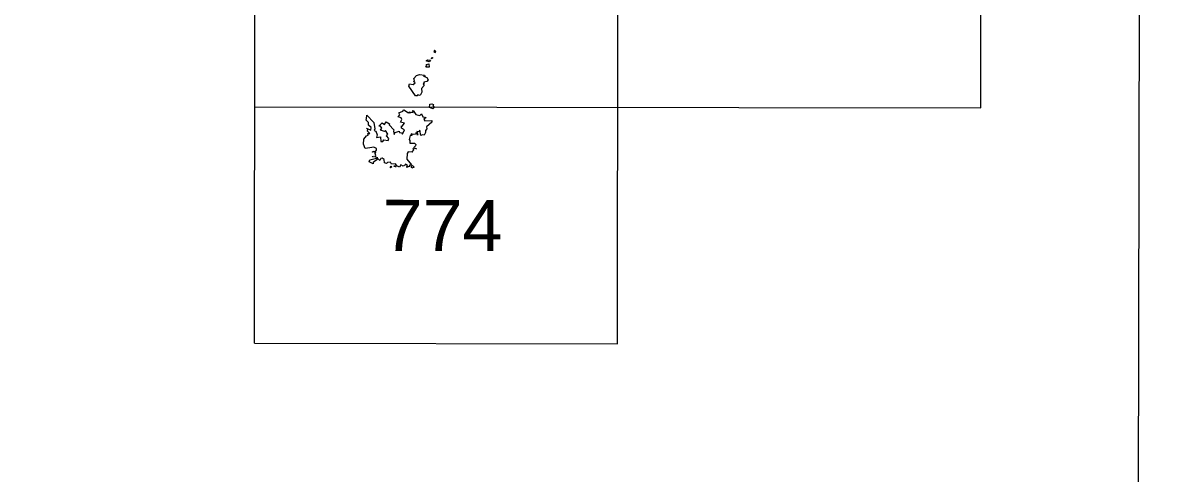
# Model space of a CAD drawing. Extents: x -807245 to 6129983, y -54972206 to 262146364.
# Drawn here: x 491598.6 to 492038.7, y 4383013.6 to 4383185.9 of the extents above; entities that cross this region are included whole.
import ezdxf
from ezdxf.enums import TextEntityAlignment as Align

# ---------------------------------------------------------------- set-up
doc = ezdxf.new("R2010")
doc.units = 0
doc.header["$LTSCALE"] = 4
doc.linetypes.add('DOTTED', pattern=[1.5, 0.3, -1.2])
for name, color, linetype, lineweight in [('1', 7, 'Continuous', 13), ('2', 7, 'DOTTED', 13), ('27', 7, 'Continuous', 25), ('3', 7, 'Continuous', 25)]:
    doc.layers.add(name, color=color, linetype=linetype, lineweight=lineweight)

msp = doc.modelspace()

# ---------------------------------------------------------------- linework, layer by layer
at = {"layer": '1', "lineweight": 25}
for p, q in [((491686.92, 4383063.58), (491687.71, 4383605.53)), ((491825.48, 4383063.38), (491826.27, 4383605.33)), ((491964.17, 4383153.49), (491964.83, 4383605.13)), ((491687.05, 4383153.89), (491964.17, 4383153.49)), ((491686.92, 4383063.57), (491825.48, 4383063.37))]:
    msp.add_line(p, q, dxfattribs=at)
msp.add_lwpolyline([(487426.46, 4384475.71), (492026.46, 4384469.03), (492021.81, 4381264.03), (487421.81, 4381270.71)], close=True, dxfattribs=at)
at = {"layer": '27'}
msp.add_spline([(491255.21, 4383970.03), (491244.34, 4383967.52), (491230.36, 4383957.66), (491230.81, 4383957.81), (491230.81, 4383957.81), (491220.15, 4383951.47), (491212.7, 4383943.01), (491205.06, 4383944.23), (491184.85, 4383957.71), (491152.82, 4383981.27), (491128.36, 4384004.58), (491128.29, 4384004.88), (491122.26, 4384021.39), (491095.75, 4384034.59), (491071.07, 4384059.32), (491064.71, 4384065.12)], degree=3, dxfattribs=at)
at = {"layer": '3'}
for points in [[(491753.04, 4383171.84), (491754.17, 4383171.75), (491753.59, 4383171.07), (491752.52, 4383171.55)], [(491754.62, 4383172.8), (491755.02, 4383172.65), (491754.51, 4383172.21)], [(491755.7, 4383175.51), (491755.43, 4383174.99), (491755.98, 4383174.7), (491756.14, 4383175.02)], [(491753.57, 4383170.28), (491753.59, 4383169.01), (491752.4, 4383169.13), (491752.79, 4383169.66), (491752.46, 4383170.12)], [(491749.38, 4383143.39), (491749.18, 4383143.08), (491749.1, 4383143.54)], [(491748.39, 4383138.11), (491748.83, 4383137.91), (491748.03, 4383137.98)], [(491732.15, 4383135.07), (491732.37, 4383134.87), (491731.99, 4383134.85)], [(491738.73, 4383130.75), (491739.11, 4383131.26), (491739.43, 4383131.01), (491738.93, 4383130.55)], [(491740.34, 4383131.09), (491740.37, 4383131.47), (491741.03, 4383130.98)], [(491747.24, 4383131.44), (491747.89, 4383130.92), (491746.99, 4383130.43), (491746.79, 4383131.31)]]:
    msp.add_lwpolyline(points, close=True, dxfattribs=at)
for points in [[(491750.24, 4383158.28), (491749.31, 4383158.53), (491749.12, 4383158.16), (491748.37, 4383158.13), (491745.86, 4383161.8), (491746.1, 4383162.75), (491747.5, 4383162.4), (491748.25, 4383163.08), (491747.68, 4383163.63), (491748.04, 4383163.87), (491747.85, 4383164.75), (491748.81, 4383165.83)], [(491748.81, 4383165.83), (491749.98, 4383166.22), (491751.89, 4383166.07), (491752.14, 4383165.56), (491751.52, 4383165.57), (491752.76, 4383165.16), (491753.31, 4383164.18), (491752.7, 4383163.57), (491751.6, 4383163.28), (491751.9, 4383163.1), (491751.42, 4383162.75), (491751.77, 4383162.01), (491750.76, 4383160.97), (491750.89, 4383159.49), (491750.24, 4383158.28)], [(491753.79, 4383153.7), (491753.96, 4383154.95), (491754.68, 4383155.05), (491755.29, 4383154.82), (491755.08, 4383154.41), (491755.55, 4383153.71)], [(491730.99, 4383138.31), (491729.19, 4383138.04), (491728.58, 4383139.7), (491728.76, 4383141.61), (491729.68, 4383142.82), (491730.42, 4383143.06), (491730.27, 4383143.71), (491730.97, 4383143.72), (491730.13, 4383144.66), (491730.29, 4383145.27), (491729.71, 4383145.72), (491731.43, 4383145.06), (491731.52, 4383146.04), (491730.51, 4383146.95), (491730.44, 4383147.92), (491729.61, 4383148.81), (491729.69, 4383149.5)], [(491729.69, 4383149.5), (491729.87, 4383150.69), (491732.53, 4383147.94), (491732.88, 4383145.56), (491732.64, 4383144.82), (491733.32, 4383144.63), (491733.85, 4383143.16), (491733.53, 4383142.24), (491735.11, 4383142.51), (491735.24, 4383140.65), (491735.91, 4383140.69), (491736.32, 4383141.35), (491738, 4383141), (491738.21, 4383141.76)], [(491743.38, 4383146.58), (491744.25, 4383147.65), (491742.68, 4383148), (491743.18, 4383149.05), (491742.95, 4383149.7), (491741.85, 4383150.04), (491742.46, 4383150.82), (491742.1, 4383151.64), (491743.58, 4383152.2), (491743.92, 4383152.75), (491745.71, 4383151.67)], [(491745.71, 4383151.67), (491745.92, 4383151.97), (491746.22, 4383151.51), (491746.64, 4383151.87), (491747.6, 4383151.76), (491747.26, 4383152.15), (491747.59, 4383152.56), (491748.52, 4383151.02), (491750.09, 4383150.55), (491750.74, 4383151.18), (491751.28, 4383150.07), (491752.45, 4383149.89), (491751.6, 4383149.23), (491752.01, 4383148.54), (491754.65, 4383148.66), (491754.63, 4383148.07), (491752.61, 4383146.31), (491752.78, 4383145.51), (491752.25, 4383144.91), (491752.31, 4383144.09)], [(491755.55, 4383153.71), (491755.04, 4383153.13), (491753.79, 4383153.7)], [(491738.21, 4383141.76), (491737.42, 4383142.86), (491737.92, 4383143.51), (491736.96, 4383144.81), (491736.57, 4383144.53), (491735.08, 4383145.05), (491735.57, 4383145.82), (491735.02, 4383146.56), (491734.45, 4383146.55), (491735.76, 4383147.83), (491736.66, 4383147.18), (491737.25, 4383148.2)], [(491737.25, 4383148.2), (491738.51, 4383147.38), (491738.37, 4383147.07), (491740.22, 4383145.19), (491740, 4383144.65), (491740.32, 4383143.34), (491740.69, 4383144.08), (491742.18, 4383144.57), (491742.26, 4383144.07), (491743.13, 4383144.02), (491743.43, 4383143.41), (491744.26, 4383145.09), (491743.06, 4383145.74), (491743.14, 4383146.64), (491743.38, 4383146.58)], [(491752.31, 4383144.09), (491751.74, 4383143.05), (491750.98, 4383143.27), (491750.43, 4383142.91), (491750.05, 4383145.02), (491749.72, 4383144.3), (491748.94, 4383144.47), (491749.18, 4383143.75), (491748.57, 4383143.94), (491748.4, 4383143.51), (491747.6, 4383143.28), (491746.83, 4383143.66), (491747.06, 4383143.01), (491746.34, 4383142.91), (491745.96, 4383141.38), (491746.31, 4383141.05), (491746.31, 4383140.07)], [(491734.16, 4383134.11), (491732.27, 4383132.68), (491732.28, 4383132.19), (491730.78, 4383132.88), (491730.95, 4383133.69), (491733.99, 4383134.45), (491732.93, 4383134.86), (491733.32, 4383135.26), (491732.99, 4383136.08), (491733.32, 4383136.74), (491732.08, 4383136.65), (491732.14, 4383136.95), (491732.69, 4383136.76), (491733.54, 4383137.37), (491733.55, 4383138.03), (491732.5, 4383138.46), (491730.99, 4383138.31)], [(491746.31, 4383140.07), (491748.08, 4383140.02), (491748.5, 4383139.54), (491748.42, 4383138.97), (491747.4, 4383137.91), (491747.75, 4383137.48), (491747.19, 4383136.8), (491747.44, 4383136.63), (491745.66, 4383136.73), (491745.21, 4383136.14), (491745.1, 4383133.9), (491746.88, 4383131.73), (491746.12, 4383131.6), (491746.02, 4383130.97), (491745.64, 4383131.15), (491745.17, 4383130.74), (491745.24, 4383131.74), (491744.5, 4383132.07)], [(491744.5, 4383132.07), (491744.67, 4383131.74), (491743.73, 4383131.26), (491742.83, 4383131.74), (491742.31, 4383130.84), (491741.27, 4383131.36), (491740.82, 4383132.09), (491739.22, 4383131.99), (491738.84, 4383132.77), (491737.77, 4383132.67), (491737.37, 4383132.22), (491736.63, 4383132.48), (491736.42, 4383133.76), (491735.73, 4383134.24), (491735.19, 4383134.15), (491734.86, 4383133.41), (491734.16, 4383134.11)]]:
    msp.add_lwpolyline(points, dxfattribs=at)

# ---------------------------------------------------------------- texts
at = {"layer": '2', "width": 1.05}
msp.add_text('774', height=19.5, rotation=359.917, dxfattribs=at).set_placement((491758.75, 4383098.86), align=Align.CENTER)

doc.saveas('drawing.dxf')
